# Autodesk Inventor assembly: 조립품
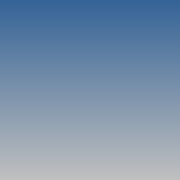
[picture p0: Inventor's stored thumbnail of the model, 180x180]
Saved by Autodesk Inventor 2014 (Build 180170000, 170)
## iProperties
Created: 2017-06
Part Number: 조립품
Document SubType Name: Assembly
Designer: 부인급구
Author: 부인급구
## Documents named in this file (1)
- C:\Users\Administrator\Desktop\470607V1005\조립품.iam
